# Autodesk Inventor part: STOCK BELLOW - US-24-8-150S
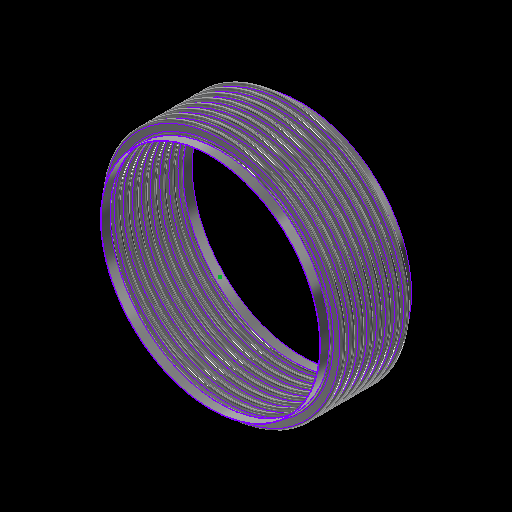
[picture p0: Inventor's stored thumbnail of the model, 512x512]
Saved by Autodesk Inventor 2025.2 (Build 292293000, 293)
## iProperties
Category: 16 GA (0.060 THICK)
RuleStatus: InUse
Created: 2024-01
Part Number: STOCK BELLOW - US-24-8-150S
Project: =STOCK BELLOWS: <Stock Number><SFILL>
Material: ASTM A240-304
Description: =STOCK BELLOWS: <Stock Number>, <SID_> I.D., <SOD_> O.D., <SPLY_> PLY, <Category>, <SNET_CONS> CONS.<PITCH_><STANGENT_> TANGENT<SFILL>
Document SubType Name: Sheet Metal
Designer: GS
Stock Number: U.S-24-8-150S
Surface Area: 26288.5 cm^2
Volume: 1989.8 cm^3
Sheet Metal Rule: Default
Appearance: STAINLESS STEEL
Mass: 16032.4 g
Density: 8.05729 g/cm^3
THK: 0.036
ID: 3.500
OD: 4.250
CONS_: 2
PITCH: 0.500
TANGENT: 0.500
BELLOWS_UPSET: 0.000
d79: 1.000
d82: 1.000
d83: 26.000
d84: 24.000
d174: 8
d214: 8
STHK_: 0.060
SID_: 24.000
SOD_: 26.500
SPITCH_: 1.000
STANGENT__: 1.000
SBELLOWS_UPSET_: 0.000
SDIFF_TAN: 1.000
d252: 2
d275: 2
d287: 0.050
d289: 0.500
d290: 0.000
SOD_NECK: 24 1/8
PLY: 1
PSET: 4.178
PBAR: 1.035
COUNTER: 1.500
NET_TUBE: 3.071
CONS: 2
S_CONS: 0
NET_CONS: 2
ID_M: 88.90 mm
OD_M: 107.95 mm
THK_M: 0.91 mm
ID_U: 3.500 in
OD_U: 4.250 in
THK_U: 0.036 in
TANGENT2: 0.500
TAN_TO_TAN: 1.000 in
d80: 2.571
d81: 10
SID: 2.375
SCONS_: 8
SPITCH: 0.250
STANGENT_: 1.000
SBELLOWS_UPSET: 0.000
SNET_CONS: 8
SS_CONS: 0
SCONS: 8
d190: 8
d191: 1
d192: 1
d193: 8
d194: 0
SIZE: 24.00
PRESSURE: 150
d230: 8
STANGENT: 4.000
SPLY_: 1
d233: 8
d234: 0
d263: 2
d265: 1
d268: 2
d269: 0
d286: 2
d288: 1
d291: 2
d292: 0
SREROLL: 0.750
BLETP: 0.000 ul
PRES_Copy: 85
MATTABLE: 20 GA (0.036 THICK)
PART_NUMBER: U.S-24-8-150S
PITCH_: =, <SPITCH_> PITCH,
CFILL: .
SFILL: .
MESH: ,
COMP: 1.47
EXT: 0.74
LAT: 0.11
ANG: 286
ASR: 6792
LSR: 91337
ANSR: 8502
PRES: 150
COMPM: 14.7
EXTM: 7.35
LATM: 1.10
ASRM: 1189.483
PRESM: 10.342
LSRM: 15995.849
ANSRM: 1488.955
TEMPMIN: 20
TEMPMAX: 800
TEMPMINM: -7
TEMPMAXM: 427
WEIGHTM: 16.032
WEIGHT: 35.345
Author: GS
Keywords: 20 GA (0.036 THICK)
Comments: =STOCK BELLOW - <STOCK NUMBER>
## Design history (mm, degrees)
sketch "Sketch2"
  geometry: L1 (0, -177.245)-(0, 562.856) reference; L2 (45.364, 0)-(44.45, 0); L3 (48.082, -2.718)-(50.343, -2.718); L4 (48.082, -3.632)-(50.343, -3.632); L5 (50.343, -9.982)-(48.082, -9.982); L6 (50.343, -9.068)-(48.082, -9.068); L7 (45.364, -12.7)-(44.45, -12.7); L8 (48.082, 0)-(48.082, -12.7); L9 (50.343, -6.35)-(53.975, -6.35); L10 (44.45, 0)-(44.45, -12.7); L11 (20.376, 102.841)-(20.376, 101.926); L12 (58.262, 457.127)-(58.262, 349.177); L13 (58.262, 444.427)-(58.262, 336.477); L14 (93.133, -58.817)-(93.133, -71.517); L15 (118.746, -66.401)-(118.746, -66.401); L16 (50.343, -9.068)-(50.343, -9.982); L17 (48.082, -9.068)-(48.082, -9.982); L18 (48.082, -9.525)-(50.343, -9.525); L19 (53.975, 0)-(53.975, -12.7); L20 (-50.343, -9.068)-(-50.343, -9.982); L21 (-50.343, -2.718)-(-48.082, -2.718); L22 (-50.343, -3.632)-(-48.082, -3.632); L23 (-48.082, -9.068)-(-50.343, -9.068); L24 (-50.343, -9.525)-(-48.082, -9.525); L25 (-48.082, -9.982)-(-50.343, -9.982); L26 (-48.082, -9.068)-(-48.082, -9.982); L27 (-44.45, 0.653)-(-44.45, -12.047); L28 (-48.082, -6.35)-(-44.45, -6.35); L29 (-50.343, 0.653)-(-50.343, -12.7); L30 (-53.061, 0)-(-53.975, 0); L31 (-53.975, 0)-(-53.975, -12.7); L32 (-53.061, -12.7)-(-53.975, -12.7); A1 r 2.718 centre (48.082, 0) between (45.364, 0) and (48.082, -2.718); A2 r 3.632 centre (48.082, 0) between (44.45, 0) and (48.082, -3.632); A3 r 3.632 centre (50.343, -6.35) between (50.343, -9.982) and (50.343, -2.718); A4 r 2.718 centre (50.343, -6.35) between (50.343, -9.068) and (50.343, -3.632); A5 r 2.718 centre (48.082, -12.7) between (48.082, -9.982) and (45.364, -12.7); A6 r 3.632 centre (48.082, -12.7) between (48.082, -9.068) and (44.45, -12.7); A7 r 3.175 centre (50.343, -6.35) between (50.343, -9.525) and (53.518, -6.35); A8 r 3.175 centre (48.082, -12.7) between (48.082, -9.525) and (44.907, -12.7); A9 r 2.718 centre (-50.343, -12.7) between (-50.343, -9.982) and (-53.061, -12.7); A10 r 2.718 centre (-48.082, -6.35) between (-48.082, -9.068) and (-48.082, -3.632); A11 r 3.175 centre (-48.082, -6.35) between (-48.082, -9.525) and (-44.907, -6.35); A12 r 3.632 centre (-48.082, -6.35) between (-48.082, -9.982) and (-48.082, -2.718); A13 r 3.175 centre (-50.343, -12.7) between (-50.343, -9.525) and (-53.518, -12.7); A14 r 3.632 centre (-50.343, -12.7) between (-50.343, -9.068) and (-53.975, -12.7); A15 r 2.718 centre (-50.343, 0) between (-53.061, 0) and (-50.343, -2.718); A16 r 3.632 centre (-50.343, 0) between (-53.975, 0) and (-50.343, -3.632); 10 further points
  constraints: 62 end point, 38 point on circle, 20 tangent, 16 centre point, 12 parallel, 9 midpoint, 7 vertical, 6 coincident, 6 concentric, 6 point on line, 4 equal radius, 4 perpendicular, 3 horizontal, 1 collinear, 1 horizontal alignment, 10 other
  dimensions: "THK" = 0.9144 distance of L11.start L11.end; "ID" = 88.9 distance of L11.end point (20.376, 13.026); "OD" = 107.95 distance of L12.start L12.end; "PITCH" = 12.7 distance of L12.start L13.start; "TANGENT" = 12.7 distance of L14.start L14.end; "BELLOWS_UPSET" = 0 distance of L15.start L15.end; "d43" = 88.9 diameter of L10 L1 (= ID); "d44" = 107.95 diameter of L9.end L1 (= OD); "d45" = 0.9144 distance between parallel lines of L5 L6 (computed from THK, PLY); "d46" = 3.6322 radius of A3 (computed from PITCH, THK, PLY); "UPSET_PITCH" = 12.7 distance of L2.end L7.end (derived); "SIDEWALL_ANGLE" = 360 deg dimension on L3 L9 (derived); "CON_GAP" = 5.4356 distance of point (48.082, -9.068) point (48.082, -3.632) (derived); "TAN1" = 4.98728 dimension on A8 (derived); "TAN2" = 4.98728 dimension on A7 (derived); "LEG1" = 2.2606 distance of L18.start L18.end (derived); "d278" = 0.9144 distance between parallel lines of L25 L23 (derived); "d279" = 3.6322 radius of A12 (derived); "d280" = 12.7 distance of L30.end L31.end (derived); "d281" = 360 deg dimension on L21 L28 (derived); "d282" = 5.4356 distance of point (-50.343, -9.068) point (-50.343, -3.632) (derived); "d283" = 4.98728 dimension on A13 (derived); "d284" = 4.98728 dimension on A11 (derived); "d285" = 2.2606 distance of L24.start L24.end (derived); "d293" = 88.9 diameter of L27 L1 (derived); "d294" = 107.95 diameter of L31 L1 (derived)
  node "Sketch Rectangular Pattern1" dims "d31" = 25.4, "ID" = 88.9
  node "Sketch Rectangular Pattern2" dims "d39" = 25.4, "PITCH" = 12.7
revolve "CONS" stored, may be unused: angle "d48" = 90 deg
node "BELLOW MIDPLANE"
pattern_linear "Rectangular Pattern2" dims "d52" = 12.7 (= UPSET_PITCH)
sketch "Sketch5"
  geometry: C1 r 45.364 at (0, 0) reference; C2 r 44.45 at (0, 0) reference
extrude "TANGENT" new body sketch "Sketch5" distance "d53" = 12.7 (= TANGENT); taper "d54" = 0 deg
revolve "SAMETAN" stored, may be unused: angle "d65" = 90 deg
revolve "DIFFTAN" stored, may be unused: angle "d70" = 90 deg
sketch "Sketch9"
  geometry: L1 (53.319, 0)-(-53.319, 0) reference; L2 (0, -17.78)-(0, 17.78) reference; L3 (38.085, 0)-(-38.085, 0); L4 (38.085, -11.906)-(38.085, 11.906); L5 (25.385, -11.906)-(25.385, 11.906); L6 (13.15, 11.906)-(13.15, -11.906); L7 (-25.385, -11.906)-(-25.385, 11.906); L8 (-38.085, -11.906)-(-38.085, 11.906); L9 (37.291, -11.906)-(37.291, 11.906); L10 (38.085, -11.906)-(37.291, -11.906); L11 (38.085, 11.906)-(37.291, 11.906); L12 (13.546, 11.906)-(12.753, 11.906); L13 (12.753, 11.906)-(12.753, -11.906); L14 (12.753, -11.906)-(13.546, -11.906); L15 (13.546, -11.906)-(13.546, 11.906); L16 (-13.546, 11.906)-(-13.546, -11.906); L17 (-13.15, 11.906)-(-13.15, -11.906); L18 (-13.546, -11.906)-(-12.753, -11.906); L19 (-12.753, -11.906)-(-12.753, 11.906); L20 (-12.753, 11.906)-(-13.546, 11.906); L21 (-38.085, -11.906)-(-37.291, -11.906); L22 (-37.291, -11.906)-(-37.291, 11.906); L23 (-37.291, 11.906)-(-38.085, 11.906); L24 (-38.085, 11.906)-(-38.085, -11.906); L25 (38.085, -0.397)-(-38.085, -0.397); L26 (-38.085, -0.397)-(-38.085, 0.397); L27 (-38.085, 0.397)-(38.085, 0.397); L28 (38.085, 0.397)-(38.085, -0.397); L29 (-38.085, 11.906)-(38.085, 11.906); L30 (38.085, 11.906)-(38.085, 12.7); L31 (38.085, 12.7)-(-38.085, 12.7); L32 (-38.085, 12.7)-(-38.085, 11.906); L33 (38.085, -11.906)-(-38.085, -11.906); L34 (-38.085, -11.906)-(-38.085, -12.7); L35 (-38.085, -12.7)-(38.085, -12.7); L36 (38.085, -12.7)-(38.085, -11.906); 30 further points
  constraints: 68 end point, 13 midpoint, 13 parallel, 8 horizontal, 7 perpendicular, 6 equal length, 3 point on line, 2 vertical, 14 other
  dimensions: "d115" = 23.8125 distance of L4.start L4.end (derived); "d116" = 12.7 distance between parallel lines of L4 L5 (derived); "d117" = 12.23516 distance between parallel lines of L5 L6 (derived); "d125" = 38.53427 distance between parallel lines of L7 L6 (derived); "d127" = 12.7 distance between parallel lines of L8 L7 (derived); "d128" = 24.93516 distance between parallel lines of L6 L4 (derived); "d130" = 76.16943 distance between parallel lines of L8 L4 (derived); "RULER_THK" = 0.79375 distance between parallel lines of L4 L9; "d135" = 0.79375 distance of L13.end L14.end (derived); "d138" = 26.29911 distance of L13.end L16.end (derived); "d143" = 0.79375 distance of L22.end L8.end (derived); "d144" = 0.79375 distance between parallel lines of L27 L25 (derived)
extrude "RULER" join sketch "Sketch9" distance "d149" = 0.79375 (derived); taper "d150" = 0 deg
extrude "BARS" join sketch "Sketch9" distance "d151" = 0.79375 (derived); taper "d152" = 0 deg
pattern_linear "Rectangular Pattern4" dims "d155" = 26.29911 (derived)
sketch "Sketch13"
  geometry: L1 (93.149, -52.467)-(93.149, -77.867); L2 (306.324, 0)-(304.8, 0); L3 (306.324, -25.4)-(304.8, -25.4); L4 (329.438, -19.812)-(311.912, -19.812); L5 (329.438, -18.288)-(311.912, -18.288); L6 (329.438, -12.7)-(336.55, -12.7); L7 (311.912, -5.588)-(329.438, -5.588); L8 (311.912, 0)-(311.912, -25.4); L9 (304.8, 0)-(304.8, -25.4); L10 (58.254, 176.669)-(58.254, -496.431); L11 (58.254, 151.269)-(58.254, -521.831); L12 (58.254, 100.469)-(58.254, -572.631); L13 (58.254, 75.069)-(58.254, -598.031); L14 (58.254, 49.669)-(58.254, -623.431); L15 (58.254, 24.269)-(58.254, -648.831); L16 (58.254, -1.131)-(58.254, -674.231); L17 (58.254, 125.869)-(58.254, -547.231); L18 (20.376, 103.45)-(20.376, 101.926); L19 (311.912, -7.112)-(329.438, -7.112); L20 (0, -844.411)-(0, 346.849) reference; L21 (-67.31, 0)-(403.86, 0) reference; A1 r 5.588 centre (311.912, 0) between (306.324, 0) and (311.912, -5.588); A2 r 5.588 centre (311.912, -25.4) between (311.912, -19.812) and (306.324, -25.4); A3 r 7.112 centre (311.912, -25.4) between (311.912, -18.288) and (304.8, -25.4); A4 r 5.588 centre (329.438, -12.7) between (329.438, -18.288) and (329.438, -7.112); A5 r 7.112 centre (329.438, -12.7) between (329.438, -19.812) and (329.438, -5.588); A6 r 7.112 centre (311.912, 0) between (304.8, 0) and (311.912, -7.112); 6 further points; 1 other entity
  constraints: 38 end point, 15 point on circle, 9 tangent, 6 centre point, 6 parallel, 5 vertical alignment, 4 point on line, 4 vertical, 3 coincident, 3 concentric, 2 collinear, 2 equal radius, 1 horizontal, 1 perpendicular, 23 other
  dimensions: "SBELLOWS_UPSET_" = 0 distance of point (118.762, -66.401) point (118.762, -66.401); "STOTAL_THK_BELLOW__" = 1.524 distance between parallel lines of L4 L5 (derived); "d224" = 7.112 radius of A5 (derived); "d225" = 25.4 distance of L2.end L3.end (derived); "SSIDEWALL_ANGLE_" = 360 deg dimension on L7 L6 (derived); "SSCON_GAP_" = 11.176 distance of point (311.912, -18.288) point (311.912, -7.112) (derived); "d235" = 609.6 diameter of L9 L20 (derived); "d236" = 673.1 diameter of L6.end L20 (derived)
  node "Sketch Rectangular Pattern4" dims "d228" = 25.4
  node "Sketch Rectangular Pattern5" dims "d229" = 25.4
revolve "SBELLOW" stored, may be unused: angle "d197" = 90 deg
pattern_linear "Rectangular Pattern5" dims "d204" = 25.4 (derived)
revolve "STANGENT" stored, may be unused: angle "d240" = 90 deg
revolve "SSAMETAN" stored, may be unused: angle "d241" = 90 deg
revolve "SDIFFTAN" stored, may be unused: angle "d246" = 90 deg
revolve "INVCON" stored, may be unused: angle "d295" = 90 deg
pattern_linear "Rectangular Pattern6" dims "d298" = 12.7 (derived)
revolve "INVTANGENT" stored, may be unused: angle "d302" = 90 deg
revolve "INVSAMETAN" stored, may be unused: angle "d307" = 90 deg
revolve "INVDIFFTAN" stored, may be unused: angle "d312" = 90 deg
sketch "ID BELLOW MOUNT CALC"
  geometry: L1 (44.45, 0)-(38.1, 0); L2 (38.1, 0)-(38.1, 12.7); L3 (38.1, 12.7)-(44.45, 12.7); L4 (44.45, 12.7)-(44.45, 0); L5 (36.513, 12.7)-(35.598, 12.7); L6 (35.598, 12.7)-(35.598, 0); L7 (35.598, 0)-(36.513, 0); L8 (36.513, 0)-(36.513, 12.7); L9 (0, -2.54)-(0, 15.24) reference; L10 (-8.89, 0)-(53.34, 0) reference; 1 further point
  constraints: 16 end point, 5 parallel, 2 collinear, 2 horizontal, 2 perpendicular
  dimensions: "d314" = 12.7 distance of L5.end L6.end (derived); "d315" = 0.9144 distance of L5.start L5.end (derived); "IG" = 1.5875 distance between parallel lines of L2 L8; "PIPE_OD" = 88.9 diameter of L4 L9; "PIPE_WALL" = 6.35 distance of L2.end L3.end; "ID_MT_BELLOW" = 71.1962 diameter of L6 L9 (derived)
revolve "CFILL" stored, may be unused: angle "d320" = 90 deg
pattern_linear "Rectangular Pattern7" dims "d323" = 12.7 (derived)
revolve "SFILL" stored, may be unused: angle "d324" = 90 deg
pattern_linear "Rectangular Pattern8" dims "d327" = 25.4 (derived)
node "STOCK BELLOW MIDPLANE"
node "BELLOW"
sketch "Sketch6"
  geometry: L1 (-12.7, 45.364)-(0, 45.364); L2 (0, 45.364)-(0, 44.45); L3 (0, 44.45)-(-12.7, 44.45); L4 (-12.7, 44.45)-(-12.7, 45.364); L5 (10.16, 0)-(-60.96, 0) reference; L6 (-38.1, -89.422)-(-38.1, 153.44) reference; 1 further point
  constraints: 8 end point, 2 parallel, 1 horizontal, 1 perpendicular
  dimensions: "d61" = 12.7 distance of L2.end L3.end (derived); "d62" = 0.9144 distance of L1.end L2.end (derived); "d63" = 88.9 diameter of L3 L5 (derived); "d64" = 25.4 distance between parallel lines of L4 L6 (derived)
sketch "Sketch12"
  geometry: 1 further point
sketch "Sketch14"
  geometry: L1 (-25.4, 306.324)-(0, 306.324); L2 (0, 306.324)-(0, 304.8); L3 (0, 304.8)-(-25.4, 304.8); L4 (-25.4, 304.8)-(-25.4, 306.324); L5 (5.08, 0)-(-30.48, 0) reference; L6 (0, -61.265)-(0, 367.589) reference; 1 further point
  constraints: 8 end point, 2 parallel, 1 collinear, 1 horizontal, 1 perpendicular
  dimensions: "d237" = 1.524 distance of L3.end L1.start (derived); "d238" = 609.6 diameter of L3 L5 (derived); "d239" = 25.4 distance of L1.start L1.end (derived); "SOD_NECK" = 612.648 diameter of L1 L5 (derived)
sketch "Sketch15"
  geometry: L1 (-61.265, 0)-(367.589, 0) reference; L2 (304.8, -203.2)-(306.324, -203.2); L3 (306.324, -203.2)-(306.324, -228.6); L4 (306.324, -228.6)-(304.8, -228.6); L5 (304.8, -228.6)-(304.8, -203.2); L6 (0, -276.86)-(0, 60.96) reference; 1 further point
  constraints: 8 end point, 2 parallel, 1 horizontal, 1 perpendicular
  dimensions: "d205" = 25.4 distance of L4.end L2.start (derived); "d206" = 1.524 distance of L3.end L4.end (derived); "d207" = 609.6 diameter of L5 L6 (derived); "d208" = 203.2 distance between parallel lines of L1 L2 (derived)
node "TANGENT_"
node "SAME_TAN"
sketch "Sketch8"
  geometry: L1 (45.364, -25.4)-(44.45, -25.4); L2 (44.45, -25.4)-(44.45, -38.1); L3 (44.45, -38.1)-(45.364, -38.1); L4 (45.364, -38.1)-(45.364, -25.4); L5 (0, -48.26)-(0, 22.86) reference; L6 (-89.422, 0)-(153.44, 0) reference; 1 further point
  constraints: 8 end point, 2 parallel, 1 horizontal, 1 perpendicular
  dimensions: "d66" = 88.9 diameter of L2 L5 (derived); "TOTAL_THK_BELLOW" = 0.9144 distance of L2.end L3.end (derived); "d68" = 25.4 distance between parallel lines of L1 L6 (derived); "d69" = 12.7 distance of L1.end L2.end (derived)
node "DIFF_TAN"
node "Sketch Rectangular Pattern3" dims "d138" = 26.29911 (derived), "d141" = 25.4
node "SBELLOW_"
node "STANGENT_"
node "SSAME_TAN"
sketch "Sketch16"
  geometry: L1 (306.324, -203.2)-(304.8, -203.2); L2 (304.8, -203.2)-(304.8, -228.6); L3 (304.8, -228.6)-(306.324, -228.6); L4 (306.324, -228.6)-(306.324, -203.2); L5 (0, -276.86)-(0, 60.96) reference; L6 (-61.265, 0)-(367.589, 0) reference; 1 further point
  constraints: 8 end point, 2 parallel, 1 horizontal, 1 perpendicular
  dimensions: "SDIFF_TAN" = 25.4 distance of L3.end L1.start; "d243" = 1.524 distance of L2.end L3.end (derived); "d244" = 203.2 distance between parallel lines of L1 L6 (derived); "d245" = 609.6 diameter of L2 L5 (derived)
node "SDIFF_TAN"
body "Solid15"
sketch "Sketch17"
  geometry: L1 (53.975, 12.7)-(53.061, 12.7); L2 (53.061, 12.7)-(53.061, 0); L3 (53.061, 0)-(53.975, 0); L4 (53.975, 0)-(53.975, 12.7); L5 (0, -2.54)-(0, 15.24) reference; L6 (-10.795, 0)-(64.77, 0) reference; 2 further points
  constraints: 8 end point, 2 parallel, 1 horizontal, 1 midpoint, 1 perpendicular, 1 point on line
  dimensions: "INVTANGENT" = 12.7 distance of L3.end L1.start (derived); "d300" = 0.9144 distance of L1.start L1.end (derived); "d301" = 107.95 diameter of L4 L5 (derived)
body "Solid16"
sketch "Sketch18"
  geometry: L1 (53.975, -25.4)-(53.061, -25.4); L2 (53.061, -25.4)-(53.061, -38.1); L3 (53.061, -38.1)-(53.975, -38.1); L4 (53.975, -38.1)-(53.975, -25.4); L5 (-10.795, 0)-(64.77, 0) reference; L6 (0, -48.26)-(0, 22.86) reference; 1 further point
  constraints: 8 end point, 2 parallel, 1 horizontal, 1 perpendicular
  dimensions: "d303" = 25.4 distance between parallel lines of L1 L5 (derived); "d304" = 12.7 distance of L3.end L1.start (derived); "d305" = 0.9144 distance of L2.end L3.end (derived); "d306" = 107.95 diameter of L4 L6 (derived)
body "Solid17"
sketch "Sketch19"
  geometry: L1 (53.975, -25.4)-(53.061, -25.4); L2 (53.061, -25.4)-(53.061, -38.1); L3 (53.061, -38.1)-(53.975, -38.1); L4 (53.975, -38.1)-(53.975, -25.4); L5 (0, -48.26)-(0, 22.86) reference; L6 (-10.795, 0)-(64.77, 0) reference; 1 further point
  constraints: 8 end point, 2 parallel, 1 horizontal, 1 perpendicular
  dimensions: "d308" = 12.7 distance of L1.end L2.end (derived); "d309" = 107.95 diameter of L4 L5 (derived); "d310" = 0.9144 distance of L2.end L3.end (derived); "d311" = 25.4 distance between parallel lines of L1 L6 (derived)
body "Solid18"
body "Solid19"
body "Solid20"
other parameters: "BMPL" = -101.6, "PSET" = 106.1212 (computed from OD, THK, PLY) [user parameter], "PBAR" = 26.29911 (= 0.570796 x PITCH + OD - ID) [user parameter; used in 1 equation term], "COUNTER" = 15 [user parameter], "NET_TUBE" = 77.99823 (computed from CONS_, PBAR, TANGENT) [user parameter], "S_CONS" = 0 [user parameter; used in 1 equation term], "ID_M" = 88.9 (= ID) [user parameter], "OD_M" = 107.95 (= OD) [user parameter], "THK_M" = 0.9144 (= THK) [user parameter], "ID_U" = 88.9 (= ID) [user parameter], "OD_U" = 107.95 (= OD) [user parameter], "THK_U" = 0.9144 (= THK) [user parameter], "D_UNITS" = 0 [user parameter], "TANGENT2" = 12.7 [user parameter], "TAN_TO_TAN" = 25.4 [user parameter], "OD_NECK" = 90.7288 [user parameter], "d79" = 25.4, "d80" = 65.29823 [user parameter], "d82" = 25.4, "d83" = 660.4, "d84" = 609.6, "sa_0" = 4, "FRAME_THK" = 0.79375 [user parameter], "CON_FLAT" = 12.23516 [user parameter], "SID" = 60.325 [user parameter], "SPITCH" = 6.35 [user parameter], "STANGENT_" = 25.4 [user parameter], "SBELLOWS_UPSET" = 0 [user parameter], "SS_CONS" = 0 [user parameter], "STAN_TO_TAN_" = 203.2 [user parameter], "d100" = 1.524 [user parameter], "d191" = 25.4 [user parameter], "d194" = 0 [user parameter], "STANGENT" = 101.6 [user parameter], "d234" = 0 [user parameter], "SUPSET_PITCH_" = 25.4 [user parameter], "d269" = 0 [user parameter], "d287" = 1.27, "d289" = 12.7, "d290" = 0, "d292" = 0 [user parameter], "Thickness" = 3.048 (derived), "KFactor" = 4.4, "BendRadius" = 3.048 (derived), "BendReliefWidth" = 3.048 (derived), "BendReliefDepth" = 1.524 (derived), "CornerReliefSize" = 12.192 (derived), "SeamGap" = 0.00508, "MinimumRemnant" = 6.096 (derived), "TransitionRadius" = 3.048 (derived), "JacobiRadiusSize" = 3.048 (derived), "GapSize" = 3.048 (derived), "SREROLL" = 19.05 [user parameter], "CUR_STK_PITCH" = 25.4 [user parameter], "d328" = -101.6 (derived), "ASR" = 67920 [user parameter], "LSR" = 913370 [user parameter], "ANSR" = 85020 [user parameter], "BLETP" = 0 [user parameter], "ASRM" = 11894.8296 [user parameter], "PRESM" = 103.41975 [user parameter], "LSRM" = 159958.4881 [user parameter], "ANSRM" = 14889.5526 [user parameter], "TEMPMIN" = 2664.83333 [user parameter], "TEMPMAX" = 6998.16667 [user parameter], "TEMPMINM" = 2664.83333 [user parameter], "TEMPMAXM" = 6998.16667 [user parameter], "WEIGHT" = 160.32414 [user parameter], "WEIGHTM" = 0.16032 [user parameter]
